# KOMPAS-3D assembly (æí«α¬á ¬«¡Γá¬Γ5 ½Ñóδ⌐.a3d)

Referenced files in D:\МОДЕЛЬ ТАНКА Т90\ДЕТАЛИ\БАШНЯ\башня сварная\НАВЕСКА\: контакт5.m3d
Referenced files in D:\МОДЕЛЬ ТАНКА Т90\ДЕТАЛИ\БАШНЯ\башня сварная\: контакт5-1.m3d
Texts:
  Сборка контакт5
  stalker61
